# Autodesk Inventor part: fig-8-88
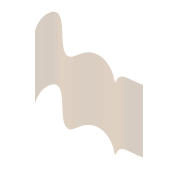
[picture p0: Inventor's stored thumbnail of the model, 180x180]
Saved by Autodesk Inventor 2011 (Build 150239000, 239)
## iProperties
Shininess: 64.0
Length Units: 11269
Angle Units: 11279
Time Units: 11290
Mass Units: 11283
Length Display Precision: 3
Angle Display Precision: 2
Compacted: True
Part Number: fig-8-88
Document SubType Name: Modeling
Created: 2003-08
Designer: Owner
Manufacturer: Standard
Standards Organization: Custom
Density: 1 g/cm^3
Density: 0.0
Volumn: 0.0
Area: 0.0
PropertySet Name: Model Information
Control State: 0
Master: False
Checked Out: False
Author: Owner
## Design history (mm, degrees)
sketch "Sketch1"
  geometry: 7 further points
  constraints: 7 other
  dimensions: "d0" = 80 horizontal distance of point (40, 1.742) point (-40, -4.065); "d1" = 40 horizontal distance of point (0, 0) point (-40, -4.065)
extrude_surface "ExtrusionSrf1" sketch "Sketch1" dims "d2" = 80, "d3" = 0
sketch "Sketch2"
  geometry: L1 (40, 0)-(40, -40) reference; L2 (-40, 0)-(-40, -40) reference; 7 further points
  constraints: 2 point on line, 7 other
extrude_surface "ExtrusionSrf2" dims "d4" = 80, "d5" = 0
split "Split6"
sketch "3D Sketch1"
feature "SweepSrf1" sketch "3D Sketch1" dims "d6" = 0
feature "Extend1" dims "d7" = 10
body "Srf1"
body "Srf2"
body "Srf3"
node "3D Intersection1"
